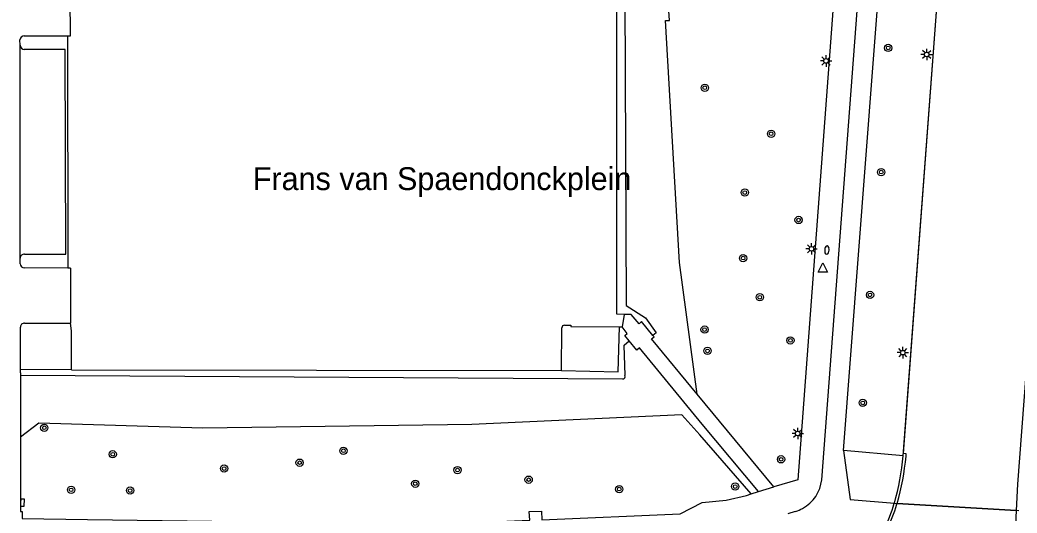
# Model space of a CAD drawing. Extents: x 132573 to 132944, y 398226 to 398676.
# Drawn here: x 132641.6 to 132750.7, y 398296.9 to 398350.8 of the extents above; entities that cross this region are included whole.
import ezdxf

# ---------------------------------------------------------------- set-up
doc = ezdxf.new("R2010")
doc.units = 0
for name, color, linetype in [('gg-afsc-hekwerk', 7, 'Continuous'), ('gg-anno-openbare ruimte label', 7, 'Continuous'), ('gg-knt-verharding', 7, 'Continuous'), ('gg-knt-verharding nz', 7, 'Continuous'), ('gt-grn-groengrens', 7, 'Continuous'), ('gt-grn-vlakafsluiter', 7, 'Continuous'), ('gt-symb-boom', 7, 'Continuous'), ('gt-symb-brandkraan', 7, 'Continuous'), ('gt-symb-kolk', 7, 'Continuous'), ('gt-symb-lichtmast', 7, 'Continuous'), ('gt-symb-waterafsluiter', 7, 'Continuous'), ('ir-asfa-asfalt arcering', 7, 'Continuous')]:
    doc.layers.add(name, color=color, linetype=linetype)

msp = doc.modelspace()

# ---------------------------------------------------------------- linework, layer by layer
at = {"layer": 'gg-afsc-hekwerk'}
for p, q in [((132647.09, 398349.1), (132647.07, 398355.33)), ((132646.76, 398349.1), (132646.8, 398323.69)), ((132647.09, 398323.69), (132647.1, 398317.67))]:
    msp.add_line(p, q, dxfattribs=at)
for points in [[(132712.22, 398350.77), (132712.66, 398350.77), (132710.12, 398386.98)], [(132647.21, 398312.54), (132647.19, 398316.84), (132647.1, 398317.67)]]:
    msp.add_lwpolyline(points, dxfattribs=at)
at = {"layer": 'gg-knt-verharding'}
for p, q in [((132730.95, 398357.23), (132726.71, 398300.53)), ((132738.26, 398303.14), (132741.94, 398352.18)), ((132641.59, 398348.06), (132641.56, 398348.65)), ((132642.04, 398349.09), (132646.76, 398349.1)), ((132646.76, 398349.1), (132647.09, 398349.1)), ((132641.6, 398324.77), (132641.59, 398348.06)), ((132641.6, 398324.17), (132641.6, 398324.77)), ((132646.8, 398323.69), (132642.05, 398323.7)), ((132647.09, 398323.69), (132646.8, 398323.69)), ((132641.62, 398312.6), (132641.61, 398317.23)), ((132642.07, 398317.67), (132647.1, 398317.67)), ((132700.85, 398312.47), (132700.88, 398317.15)), ((132707.19, 398317.26), (132707.47, 398317.26)), ((132708.26, 398315.72), (132707.78, 398316.31)), ((132709.1, 398314.71), (132708.26, 398315.72)), ((132710.99, 398316.16), (132710.86, 398316.33)), ((132641.62, 398312.24), (132641.62, 398312.6)), ((132647.21, 398312.54), (132700.85, 398312.47)), ((132641.62, 398312.24), (132641.62, 398311.96)), ((132641.62, 398311.96), (132641.63, 398306.94)), ((132724.1, 398299.75), (132715.71, 398309.88)), ((132641.63, 398306.94), (132641.63, 398305.19)), ((132722.41, 398299.23), (132716.26, 398306.63)), ((132738.26, 398303.14), (132731.71, 398303.73)), ((132726.71, 398300.53), (132724.1, 398299.75)), ((132722.41, 398299.23), (132724.1, 398299.75)), ((132721.09, 398298.82), (132721.6, 398298.98)), ((132721.6, 398298.98), (132722.41, 398299.23)), ((132725.65, 398296.83), (132726.47, 398297.08))]:
    msp.add_line(p, q, dxfattribs=at)
for points in [[(132729.33, 398300.53), (132733.6, 398357.19), (132733.53, 398360.95), (132732.83, 398365.31), (132731.43, 398369.77), (132729.92, 398373.08), (132717.8, 398394.49)], [(132707.69, 398318.62), (132706.91, 398318.63), (132706.89, 398386.25), (132696.22, 398386.27)], [(132731.71, 398303.73), (132735.79, 398357.04), (132735.76, 398361.07), (132735.01, 398365.67)], [(132642.07, 398325.22), (132646.57, 398325.2), (132646.52, 398347.6), (132642.04, 398347.6)], [(132710.86, 398316.33), (132709.62, 398317.83), (132709.34, 398317.59), (132708.47, 398318.61), (132707.69, 398318.62)], [(132701.18, 398317.43), (132701.87, 398317.43), (132701.87, 398317.28), (132707.19, 398317.26)], [(132707.78, 398316.31), (132708.05, 398316.55), (132707.47, 398317.26)], [(132715.71, 398309.88), (132710.69, 398315.95), (132710.99, 398316.16)], [(132716.26, 398306.63), (132709.37, 398314.95), (132709.1, 398314.71)], [(132641.63, 398305.19), (132641.64, 398297.06), (132641.81, 398297.06), (132641.8, 398296.3)], [(132731.71, 398303.73), (132732.43, 398298.39), (132737.28, 398297.97)], [(132641.8, 398296.3), (132648.96, 398296.18), (132684.39, 398295.72), (132687.24, 398295.7), (132689.79, 398295.78), (132697.37, 398296.11), (132697.32, 398297.05), (132698.67, 398297.11), (132698.7, 398296.16), (132713.84, 398296.79), (132716.24, 398298.03), (132718.86, 398298.29), (132721.09, 398298.82)]]:
    msp.add_lwpolyline(points, dxfattribs=at)
for centre, radius, start, end in [((132642.03, 398348.63), 0.461, 88.3919, 177.7357), ((132642.05, 398348.07), 0.468, 181.2247, 268.7753), ((132642.05, 398324.76), 0.456, 88.0916, 178.9132), ((132642.06, 398324.16), 0.461, 178.6018, 268.4096), ((132642.06, 398317.22), 0.453, 87.9082, 178.9548), ((132701.17, 398317.14), 0.292, 87.875, 177.8102), ((132708.94, 398305.98), 29.46, 344.2207, 354.4705), ((132725.29, 398300.97), 4.07, 298.6676, 353.7579), ((132725.29, 398300.95), 4.05, 286.9388, 298.7151), ((132726.6, 398300.81), 11.05, 328.439, 345.0933)]:
    msp.add_arc(centre, radius, start, end, dxfattribs=at)
at = {"layer": 'gg-knt-verharding nz'}
msp.add_line((132737.28, 398297.97), (132750.9, 398297.16), dxfattribs=at)
at = {"layer": 'gt-grn-groengrens'}
for p, q in [((132647.21, 398312.54), (132641.62, 398312.6)), ((132641.62, 398311.96), (132707.52, 398311.57))]:
    msp.add_line(p, q, dxfattribs=at)
for points in [[(132696.14, 398387.07), (132707.62, 398387.08), (132707.92, 398319.61), (132710.05, 398318.24), (132711.2, 398316.61), (132710.86, 398316.33)], [(132715.71, 398309.88), (132713.76, 398324.29), (132712.22, 398350.77)], [(132700.85, 398312.47), (132707.05, 398312.35), (132707.19, 398317.26)], [(132707.8, 398311.92), (132707.72, 398315.24), (132708.26, 398315.72)], [(132721.6, 398298.98), (132715.98, 398305.45), (132714.03, 398307.65), (132691.02, 398306.56), (132661.57, 398306.17), (132643.63, 398306.73), (132641.63, 398305.19)]]:
    msp.add_lwpolyline(points, dxfattribs=at)
msp.add_arc((132707.57, 398311.82), 0.249, 258.9391, 24.9492, dxfattribs=at)
at = {"layer": 'gt-grn-vlakafsluiter'}
msp.add_line((132707.69, 398318.62), (132707.47, 398317.26), dxfattribs=at)
at = {"layer": 'gt-symb-boom'}
for centre, radius in [((132736.61, 398347.77), 0.4), ((132736.61, 398347.77), 0.2), ((132716.53, 398343.41), 0.4), ((132716.53, 398343.41), 0.2), ((132723.79, 398338.38), 0.4), ((132723.79, 398338.38), 0.2), ((132735.84, 398334.19), 0.4), ((132735.84, 398334.19), 0.2), ((132720.91, 398331.95), 0.4), ((132720.91, 398331.95), 0.2), ((132726.8, 398328.95), 0.4), ((132726.8, 398328.95), 0.2), ((132720.72, 398324.78), 0.4), ((132720.72, 398324.78), 0.2), ((132734.62, 398320.75), 0.4), ((132722.55, 398320.5), 0.4), ((132722.55, 398320.5), 0.2), ((132734.62, 398320.75), 0.2), ((132716.51, 398316.96), 0.4), ((132716.51, 398316.96), 0.2), ((132725.9, 398315.78), 0.4), ((132725.9, 398315.78), 0.2), ((132716.83, 398314.63), 0.4), ((132716.83, 398314.63), 0.2), ((132733.82, 398308.94), 0.4), ((132733.82, 398308.94), 0.2), ((132644.23, 398306.22), 0.4), ((132644.23, 398306.22), 0.2), ((132651.72, 398303.32), 0.4), ((132676.97, 398303.7), 0.4), ((132676.97, 398303.7), 0.2), ((132651.72, 398303.32), 0.2), ((132672.18, 398302.4), 0.4), ((132672.18, 398302.4), 0.2), ((132724.88, 398302.77), 0.4), ((132724.88, 398302.77), 0.2), ((132663.91, 398301.76), 0.4), ((132663.91, 398301.76), 0.2), ((132689.47, 398301.59), 0.4), ((132689.47, 398301.59), 0.2), ((132684.84, 398300.1), 0.4), ((132697.25, 398300.54), 0.4), ((132697.25, 398300.54), 0.2), ((132647.17, 398299.43), 0.4), ((132647.17, 398299.43), 0.2), ((132653.62, 398299.35), 0.4), ((132653.62, 398299.35), 0.2), ((132684.84, 398300.1), 0.2), ((132707.17, 398299.51), 0.4), ((132707.17, 398299.51), 0.2), ((132719.86, 398299.79), 0.4), ((132719.86, 398299.79), 0.2)]:
    msp.add_circle(centre, radius, dxfattribs=at)
at = {"layer": 'gt-symb-brandkraan'}
for centre, radius, start, end in [((132730.59, 398325.61), 0.938, 158.6917, 192.4758), ((132732.51, 398324.86), 3, 158.0168, 158.6917), ((132729.92, 398325.9), 0.206, 13.1507, 158.0168), ((132729.21, 398325.71), 0.938, 338.6917, 12.4758), ((132727.2, 398325.27), 3, 12.4758, 13.1507), ((132732.6, 398326.05), 3, 192.4758, 193.1507), ((132729.88, 398325.42), 0.206, 193.1507, 338.0168), ((132727.29, 398326.46), 3, 338.0168, 338.6917)]:
    msp.add_arc(centre, radius, start, end, dxfattribs=at)
at = {"layer": 'gt-symb-kolk'}
msp.add_lwpolyline([(132641.64, 398298.03), (132641.64, 398297.65), (132642.04, 398297.65), (132642.05, 398298.4), (132641.65, 398298.4), (132641.64, 398298.03)], dxfattribs=at)
at = {"layer": 'gt-symb-lichtmast'}
for p, q in [((132740.64, 398347.24), (132740.37, 398347.5)), ((132740.82, 398347.31), (132740.82, 398347.68)), ((132740.99, 398347.24), (132741.26, 398347.5)), ((132729.56, 398346.35), (132729.18, 398346.35)), ((132729.63, 398346.52), (132729.36, 398346.79)), ((132729.81, 398346.6), (132729.81, 398346.97)), ((132729.98, 398346.52), (132730.25, 398346.79)), ((132730.06, 398346.35), (132730.43, 398346.35)), ((132740.57, 398347.06), (132740.19, 398347.06)), ((132740.64, 398346.88), (132740.37, 398346.62)), ((132740.82, 398346.81), (132740.82, 398346.43)), ((132741.26, 398346.62), (132740.99, 398346.88)), ((132741.07, 398347.06), (132741.44, 398347.06)), ((132729.63, 398346.17), (132729.36, 398345.9)), ((132729.81, 398346.1), (132729.81, 398345.72)), ((132730.25, 398345.9), (132729.98, 398346.17)), ((132727.96, 398325.79), (132727.59, 398325.79)), ((132728.04, 398325.97), (132727.77, 398326.23)), ((132728.04, 398325.61), (132727.77, 398325.35)), ((132728.21, 398326.04), (132728.21, 398326.42)), ((132728.21, 398325.54), (132728.21, 398325.17)), ((132728.39, 398325.97), (132728.65, 398326.23)), ((132728.65, 398325.35), (132728.39, 398325.61)), ((132728.46, 398325.79), (132728.84, 398325.79)), ((132738.04, 398314.61), (132737.77, 398314.88)), ((132738.21, 398314.69), (132738.21, 398315.06)), ((132738.39, 398314.61), (132738.66, 398314.88)), ((132737.96, 398314.44), (132737.59, 398314.44)), ((132738.04, 398314.26), (132737.77, 398313.99)), ((132738.21, 398314.19), (132738.21, 398313.81)), ((132738.66, 398313.99), (132738.39, 398314.26)), ((132738.46, 398314.44), (132738.84, 398314.44)), ((132726.52, 398305.77), (132726.26, 398306.03)), ((132726.7, 398305.84), (132726.7, 398306.21)), ((132726.88, 398305.77), (132727.14, 398306.03)), ((132726.45, 398305.59), (132726.08, 398305.59)), ((132726.52, 398305.41), (132726.26, 398305.15)), ((132726.7, 398305.34), (132726.7, 398304.96)), ((132727.14, 398305.15), (132726.88, 398305.41)), ((132726.95, 398305.59), (132727.33, 398305.59))]:
    msp.add_line(p, q, dxfattribs=at)
for centre in [(132740.82, 398347.06), (132729.81, 398346.35), (132728.21, 398325.79), (132738.21, 398314.44), (132726.7, 398305.59)]:
    msp.add_circle(centre, 0.25, dxfattribs=at)
at = {"layer": 'gt-symb-waterafsluiter'}
for p, q in [((132728.95, 398323.26), (132729.45, 398324.26)), ((132729.45, 398324.26), (132729.95, 398323.26)), ((132729.95, 398323.26), (132728.95, 398323.26))]:
    msp.add_line(p, q, dxfattribs=at)
at = {"layer": 'ir-asfa-asfalt arcering'}
for points in [[(132745.57, 398382.43), (132746.48, 398387.85), (132747.32, 398393.73), (132756.28, 398392.75), (132756.12, 398389.81), (132756, 398385.53), (132756.11, 398381.32), (132756.29, 398377.3), (132756.33, 398374.28), (132756.23, 398372.08), (132750.78, 398300.06), (132750.78, 398300.06), (132750.6, 398297.17), (132750.6, 398297.17), (132737.59, 398297.95)], [(132738.56, 398303.11), (132738.58, 398303.38), (132738.28, 398303.41), (132741.94, 398352.18), (132742.53, 398358.43)], [(132737.59, 398297.95), (132750.6, 398297.17), (132750.6, 398297.17), (132750.47, 398294.16), (132736.36, 398295)]]:
    msp.add_lwpolyline(points, dxfattribs=at)
for centre, radius, start, end in [((132708.94, 398305.98), 29.76, 344.3474, 354.4705), ((132726.6, 398300.81), 11.35, 329.2457, 345.0817), ((132708.94, 398305.98), 29.76, 344.2251, 344.3474)]:
    msp.add_arc(centre, radius, start, end, dxfattribs=at)

# ---------------------------------------------------------------- texts
at = {"layer": 'gg-anno-openbare ruimte label'}
msp.add_text('Frans van Spaendonckplein', height=2.5, dxfattribs=at).set_placement((132667.05, 398332.22))

doc.saveas('drawing.dxf')
